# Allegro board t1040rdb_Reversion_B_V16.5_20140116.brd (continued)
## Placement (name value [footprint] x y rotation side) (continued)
C897  0.1uF  [0402]  12.06 59.31 0 top
C898  0.1uF  [0402]  10.03 61.34 270 top
C899  1uF  [0402O]  173.29 62.65 90 bottom
C900  1uF  [0402O]  171.29 68.65 90 bottom
C901  1uF  [0402O]  171.79 61.15 0 bottom
C902  1uF  [0402O]  171.29 62.65 90 bottom
C903  1uF  [0402O]  170.29 64.65 270 bottom
C904  22uF  [0603]  136.27 108.71 0 bottom
C905  22uF  [0603]  136.27 104.52 0 top
C906  22uF  [0603]  136.27 114.81 0 bottom
C907  22uF  [0603]  136.27 104.14 0 bottom
C908  22uF  [0603]  136.27 105.66 0 bottom
C909  22uF  [0603]  136.27 113.28 0 bottom
C910  22uF  [0603]  136.27 109.09 0 top
C911  22uF  [0603]  136.27 107.19 0 bottom
C912  1uF  [0402]  166.02 116.15 270 bottom
C913  1uF  [0402]  166.02 118.25 90 bottom
C914  1uF  [0402]  166.02 111.94 270 bottom
C915  1uF  [0402]  166.02 114.05 270 bottom
C916  0.1uF  [0201]  167.32 110.04 0 bottom
C917  0.1uF  [0201]  168.92 111.64 0 bottom
C918  0.1uF  [0201]  167.32 110.84 180 bottom
C919  0.1uF  [0201]  168.92 110.84 180 bottom
C920  1500pF  [0201]  164.11 110.04 180 bottom
C921  1500pF  [0201]  164.11 110.84 0 bottom
C922  1500pF  [0201]  162.51 110.84 0 bottom
C923  1500pF  [0201]  162.51 112.44 0 bottom
C924  0.33uF  [0603]  197.87 75.31 270 top
C925  22uF  [1206]  194.06 79.76 90 bottom
C926  22uF  [1206]  216.79 136.91 90 bottom
C927  0.47uF  [0603]  218.19 132.46 270 top
C928  1uF  [0603]  196.98 83.44 0 top
C929  1uF  [0603]  217.3 140.59 0 top
C930  22uF  [1206]  196.47 79.76 90 bottom
C931  22uF  [1206]  214.38 136.91 90 bottom
C932  1uF  [0402]  221.49 132.97 90 top
C933  0.1uF  [0402]  187.96 83.57 0 bottom
C934  47uF  [0805]  208.03 132.59 0 bottom
C935  0.1uF  [0402]  203.33 80.9 270 top
C936  47uF  [0805]  208.03 134.75 0 bottom
C937  47uF  [0805]  187.71 81.92 0 bottom
C938  0.01uF  [0402]  201.17 75.82 90 top
C939  47uF  [0805]  187.71 79.76 0 bottom
C940  0.1uF  [0402]  208.28 140.72 0 bottom
C941  0.1uF  [0402]  223.65 138.05 270 top
C942  510pF  [0402]  201.8 80.39 0 top
C943  560pF  [0402]  222.12 137.54 0 top
C944  1uF  [0402]  198.37 81.79 270 bottom
C945  0.01uF  [0402]  199.39 80.77 270 bottom
C946  1uF  [0402]  218.69 138.94 270 bottom
C947  0.1uF  [0402]  219.71 137.92 270 bottom
C948  0.47uF  [0603]  23.24 116.59 90 top
C949  0.47uF  [0603]  23.24 105.79 90 top
C950  1uF  [0603]  25.53 116.46 180 top
C951  1uF  [0603]  24.13 97.66 180 top
C952  22uF  [1206]  27.05 112.14 270 bottom
C953  22uF  [1206]  24.64 112.14 270 bottom
C954  22uF  [1206]  24.64 101.35 270 bottom
C955  22uF  [1206]  27.05 101.35 270 bottom
C956  0.01uF  [0402]  19.94 116.08 270 top
C957  0.01uF  [0402]  19.94 105.28 270 top
C958  47uF  [0805]  33.4 105.66 180 bottom
C959  47uF  [0805]  33.4 112.14 180 bottom
C960  47uF  [0805]  33.4 109.98 180 bottom
C961  0.1uF  [0402]  33.15 108.33 180 bottom
C962  47uF  [0805]  33.4 103.51 180 bottom
C963  0.1uF  [0402]  33.15 97.54 180 bottom
C964  0.1uF  [0402]  17.78 111 90 top
C965  0.1uF  [0402]  17.78 100.2 90 top
C966  560pF  [0402]  19.3 111.51 180 top
C967  620pF  [0402]  19.3 100.71 180 top
C968  1uF  [0402]  22.73 110.11 90 bottom
C969  0.01uF  [0402]  21.72 111.12 90 bottom
C970  1uF  [0402]  22.73 99.31 90 bottom
C971  0.01uF  [0402]  21.72 100.33 90 bottom
C972  1uF  [0603]  60.71 84.84 90 top
C973  1uF  [0603]  62.99 84.71 180 top
C974  1uF  [0603]  24.13 86.87 180 top
C975  22uF  [1206]  62.1 80.39 270 bottom
C976  22uF  [1206]  64.52 80.39 270 bottom
C977  0.01uF  [0402]  57.4 84.33 270 top
C978  1uF  [0603]  23.24 95 90 top
C979  22uF  [1206]  24.64 90.55 270 bottom
C980  22uF  [1206]  27.05 90.55 270 bottom
C981  0.01uF  [0402]  19.94 94.49 270 top
C982  47uF  [0805]  70.87 78.23 180 bottom
C983  47uF  [0805]  70.87 80.39 180 bottom
C984  0.1uF  [0402]  70.61 76.58 180 bottom
C985  47uF  [0805]  33.4 87.12 180 bottom
C986  47uF  [0805]  33.4 95.25 180 bottom
C987  0.1uF  [0402]  32.77 95.38 180 top
C988  0.1uF  [0402]  55.24 79.25 90 top
C989  0.1uF  [0402]  17.78 89.41 90 top
C990  680pF  [0402]  56.77 79.76 180 top
C991  680pF  [0402]  19.3 89.92 180 top
C992  1uF  [0402]  60.2 78.36 90 bottom
C993  0.01uF  [0402]  59.18 79.38 90 bottom
C994  1uF  [0402]  22.73 88.52 90 bottom
C995  0.01uF  [0402]  21.72 89.54 90 bottom
C996  0.01uF  [0402]  201.93 131.19 90 top
C997  0.1uF  [0402]  107.19 78.61 0 top
C998  0.1uF  [0402]  175.89 163.7 90 top
C999  0.1uF  [0402]  184.91 163.19 0 top
C1000  0.1uF  [0603]  107.82 98.81 0 top
C1001  0.1uF  [0603]  107.82 108.97 0 top
C1002  0.1uF  [0402]  21.46 65.02 90 top
C1003  1500pF  [0201]  164.11 116.45 0 bottom
C1004  1500pF  [0201]  170.52 110.84 180 bottom
C1005  1500pF  [0201]  168.92 109.24 180 bottom
C1006  1500pF  [0201]  167.32 109.24 180 bottom
C1007  1500pF  [0201]  164.11 114.85 0 bottom
C1008  1500pF  [0201]  162.51 114.85 0 bottom
C1009  1500pF  [0201]  164.11 115.65 180 bottom
C1010  1500pF  [0201]  162.51 115.65 180 bottom
C1011  0.1uF  [0201]  160.91 117.25 180 bottom
C1012  0.1uF  [0201]  160.91 116.45 180 bottom
C1013  NFM21PC225B0J3  [NFM21]  196.98 125.35 0 top
C1014  NFM21PC225B0J3  [NFM21]  196.98 128.65 180 top
C1015  1uF  [0402]  212.34 125.22 0 top
C1016  1uF  [0402]  211.84 126.75 270 top
C1017  10uF  [0603]  201.68 126.49 90 top
C1018  0.1uF  [0402]  176.91 57.53 90 bottom
C1019  0.1uF  [0402]  176.91 72.26 180 bottom
C1020  0.1uF  [0402]  176.91 64.14 180 bottom
C1021  0.1uF  [0402]  176.91 63.12 180 bottom
C1022  0.1uF  [0402]  155.32 100.33 180 bottom
C1023  0.01uF  [0402]  45.85 132.84 180 top
C1024  0.01uF  [0402]  48.89 132.84 0 top
C1025  0.1uF  [0402]  196.47 62.48 90 bottom
C1026  0.1uF  [0201]  173.72 109.24 0 bottom
C1027  0.1uF  [0201]  170.52 112.44 180 bottom
C1028  0.1uF  [0201]  164.51 108.04 270 bottom
C1029  0.1uF  [0201]  164.11 113.25 180 bottom
C1030  0.1uF  [0201]  164.11 112.44 0 bottom
C1031  0.1uF  [0201]  162.51 111.64 180 bottom
C1032  0.1uF  [0201]  164.11 111.64 180 bottom
C1033  0.1uF  [0201]  164.11 109.24 0 bottom
C1034  0.1uF  [0201]  170.52 109.24 180 bottom
C1035  0.1uF  [0201]  162.51 113.25 180 bottom
C1036  0.1uF  [0201]  170.92 108.04 270 bottom
C1037  0.1uF  [0201]  170.52 111.64 0 bottom
C1038  0.1uF  [0201]  170.52 110.04 0 bottom
C1039  0.1uF  [0201]  168.92 110.04 0 bottom
C1040  10uF  [0603]  235.2 132.21 180 bottom
C1041  0.01uF  [0402]  235.08 133.98 90 bottom
C1044  0.1uF  [0402]  238.76 138.05 180 bottom
C1045  0.1uF  [0402]  235.58 138.94 270 bottom
C1046  0.1uF  [0402]  233.68 137.79 0 bottom
C1047  0.1uF  [0402]  233.93 135.51 0 bottom
C1048  0.1uF  [0402]  238.63 135.51 180 bottom
C1049  10uF  [0603]  233.68 129.92 270 bottom
C1050  0.1uF  [0402]  238.76 137.03 180 bottom
C1051  0.1uF  [0402]  233.3 139.83 90 bottom
C1052  0.1uF  [0402]  237.36 133.98 90 bottom
C1053  1uF  [0603]  215.9 132.59 0 top
C1054  1uF  [0603]  195.58 75.44 0 top
C1055  1uF  [0603]  24.13 108.46 180 top
C1056  1uF  [0603]  25.53 105.66 180 top
C1057  1uF  [0603]  61.59 76.71 180 top
C1058  1uF  [0603]  25.53 94.87 180 top
C1059  0.1uF  [0402]  91.44 129.16 180 bottom
C1060  0.1uF  [0402]  93.47 129.16 0 bottom
C1061  0.1uF  [0402]  91.44 123.32 180 bottom
C1062  0.1uF  [0402]  93.47 123.32 0 bottom
C1063  47uF  [0805]  187.71 77.6 0 bottom
C1064  47uF  [0805]  187.71 75.44 0 bottom
C1066  47uF  [0805]  33.4 93.22 180 bottom
C1067  47uF  [0805]  33.4 91.19 180 bottom
C1068  47uF  [0805]  33.4 89.15 180 bottom
C1069  47uF  [0805]  208.03 136.91 0 bottom
C1070  47uF  [0805]  208.03 139.06 0 bottom
C1071  0.1uF  [0402]  82.42 127.38 0 bottom
C1072  0.1uF  [0402]  80.39 127.38 180 bottom
C1073  0.1uF  [0402]  82.42 133.48 0 bottom
C1074  0.1uF  [0402]  80.39 133.48 180 bottom
C1075  10uF  [1206]  17.15 83.69 90 top
C1076  0.1uF  [0603]  16.76 73.79 270 top
C1077  10uF  [1206]  19.56 83.69 90 top
C1078  0.01uF  [0402]  18.03 73.91 270 top
C1079  0.1uF  [0402]  200.41 126.49 90 top
C1080  220uF  [CAPE_B8]  262.38 161.92 180 top
C1081  0.1uF  [0402]  271.65 153.54 0 bottom
C1082  0.1uF  [0402]  207.14 62.74 180 bottom
C1083  0.1uF  [0402]  214.88 70.1 90 bottom
C1084  0.1uF  [0402]  213.61 69.22 90 bottom
C1085  0.1uF  [0402]  241.43 62.74 180 bottom
C1086  0.1uF  [0402]  248.03 66.68 180 bottom
C1087  0.1uF  [0402]  248.03 67.69 180 bottom
C1088  1uF  [0402O]  167.29 64.65 90 bottom
C1089  1uF  [0402O]  166.29 66.65 90 bottom
C1090  1uF  [0402O]  167.29 66.65 90 bottom
C1091  1uF  [0402O]  165.29 68.65 90 bottom
C1092  1uF  [0402O]  166.29 68.65 90 bottom
C1093  1uF  [0402O]  167.29 68.65 90 bottom
C1094  1uF  [0402O]  170.29 68.65 90 bottom
C1095  47uF  [0805]  33.4 116.46 180 bottom
C1096  47uF  [0805]  33.4 114.3 180 bottom
C1097  47uF  [0805]  33.4 101.35 180 bottom
C1098  47uF  [0805]  33.4 99.19 180 bottom
C1099  47uF  [0805]  70.87 84.71 180 bottom
C1100  47uF  [0805]  70.87 82.55 180 bottom
C1101  0.1uF  [0402O]  65.52 105.93 0 bottom
C1102  0.1uF  [0402O]  64.02 104.42 90 bottom
C1103  0.1uF  [0402O]  65.02 104.42 90 bottom
C1104  0.1uF  [0402O]  71.52 112.93 180 bottom
C1105  0.1uF  [0402O]  71.52 113.93 0 bottom
C1106  22uF  [0603]  136.27 110.62 0 top
C1107  22uF  [0603]  136.27 112.14 0 top
C1108  22uF  [0603]  140.21 104.9 270 bottom
C1109  22uF  [0603]  141.73 104.9 270 bottom
C1110  22uF  [0603]  141.73 109.47 90 bottom
C1111  22uF  [0603]  140.21 109.47 90 bottom
C1112  22uF  [1206]  28.45 94.36 0 bottom
C1113  22uF  [1206]  21.21 94.36 180 bottom
D1  GRN  [LED_0603]  71.63 91.69 90 top
D3  CMHD3595  [SOD123]  58.93 23.62 180 top
D4  CMHD3595  [SOD123]  65.28 27.94 90 top
D5  GRN  [LED_0603]  40.89 84.84 180 top
D6  GRN  [LED_0603]  40.89 82.55 180 top
D22  RB521  [SOD523]  117.86 28.58 180 top
D25  ES1D-13-F  [SMA]  38.1 76.33 90 top
D26  MURS120-13-F  [SMB]  49.15 49.66 180 top
D27  BAW56-7-F  [SOT23]  71.12 50.55 180 bottom
D28  MURS120-13-F  [SMB]  50.29 55.88 90 top
D30  RB521  [SOD523]  77.85 147.07 0 top
D31  RB521  [SOD523]  69.98 151.38 270 top
D33  BAT43WS  [SOD323]  58.17 135.25 270 top
D34  RB521  [SOD523]  58.42 126.75 180 top
D35  RB521  [SOD523]  15.62 62.99 0 top
D36  GRN  [LED_PM_1S]  53.72 1.14 0 top
D37  GRN  [LED_PM_1S]  58.04 1.14 0 top
D38  GRN  [LED_PM_1S]  32.13 1.14 0 top
D39  GRN  [LED_PM_1S]  36.45 1.14 0 top
D40  GRN  [LED_PM_1S]  49.4 1.14 0 top
D41  GRN  [LED_PM_1S]  40.77 1.14 0 top
D42  GRN  [LED_PM_1S]  45.09 1.14 0 top
D43  GRN  [LED_PM_1S]  27.81 1.14 0 top
D44  GRN  [LED_PM_1S]  23.49 1.14 0 top
F1  3A/60V  [PTC_SM013]  96.27 31.5 270 top
F2  3A/60V  [PTC_SM013]  91.82 31.5 270 top
F3  3A/60V  [PTC_SM013]  87.38 31.5 270 top
F4  3A/60V  [PTC_SM013]  82.93 31.5 270 top
F5  3A/60V  [PTC_SM013]  114.05 31.5 270 top
F6  3A/60V  [PTC_SM013]  109.6 31.5 270 top
F7  3A/60V  [PTC_SM013]  105.16 31.5 270 top
F8  3A/60V  [PTC_SM013]  100.71 31.5 270 top
F9  500mA  [1206]  34.67 241.05 0 top
F10  500mA  [1206]  64.26 137.79 0 top
F11  500mA  [1206]  174.37 241.05 0 top
F12  500mA  [1206]  104.52 241.05 0 top
F13  500mA  [1206]  244.22 241.05 0 top
FB6  BLM21PG121SN1  [0805]  66.42 19.56 90 top
FB7  BLM21PG121SN1  [0805]  73.53 19.56 90 bottom
FB8  BLM21PG121SN1  [0805]  64.39 19.56 90 top
FB9  BLM21PG121SN1  [0805]  73.53 19.56 90 top
FB10  BLM18BD601SN1  [0603]  80.14 89.66 90 top
FB11  BLM18PG121SN1  [0603]  161.92 98.3 270 bottom
FB12  BLM18PG121SN1  [0603]  159.64 98.04 0 bottom
FB13  BLM18PG121SN1  [0603]  156.59 98.04 180 bottom
FB18  BLM18BD601SN1  [0603]  122.94 39.5 0 top
FB19  BLM18BD601SN1  [0603]  122.94 36.45 0 top
FB20  BLM18BD601SN1  [0603]  122.94 37.97 0 top
FB21  BLM18BD601SN1  [0603]  122.94 34.92 0 top
FB22  BLM18BD601SN1  [0603]  122.94 30.35 0 top
FB23  BLM18BD601SN1  [0603]  122.94 31.88 0 top
FB24  BLM18BD601SN1  [0603]  122.94 28.83 0 top
FB25  BLM18BD601SN1  [0603]  122.94 33.4 0 top
FB26  BLM18BD601SN1  [0603]  166.24 43.56 0 top
FB29  BLM18BD601SN1  [0603]  135 41.66 270 top
FB32  BLM18BD601SN1  [0603]  184.91 54.36 270 top
FB35  BLM18PG121SN1  [0603]  218.44 73.66 270 bottom
FB36  BLM18PG121SN1  [0603]  203.2 64.52 180 bottom
FB37  BLM18PG121SN1  [0603]  252.73 73.66 270 bottom
FB38  BLM18PG121SN1  [0603]  237.49 64.52 180 bottom
FB39  BLM18BD601SN1  [0603]  260.99 62.74 270 top
FB40  BLM18PG121SN1  [0603]  175.64 57.15 90 bottom
FB41  BLM18PG121SN1  [0603]  177.29 70.99 180 bottom
FB42  BLM18PG121SN1  [0603]  177.29 65.41 180 bottom
FB43  BLM18PG121SN1  [0603]  177.29 61.85 180 bottom
FB44  BLM21PG121SN1  [0805]  178.31 48.51 270 bottom
FB45  BLM21PG121SN1  [0805]  176.28 48.51 270 bottom
FB46  BLM21PG121SN1  [0805]  59.82 45.59 0 top
FB47  BLM18BD601SN1  [0603]  47.88 112.65 0 top
FB48  BLM18BD601SN1  [0603]  80.14 98.17 90 top
FB50  BLM18BD601SN1  [0603]  80.14 106.55 90 top
FB52  BLM18BD601SN1  [0603]  153.16 71.76 0 top
FB53  BLM18BD601SN1  [0603]  234.82 77.98 180 top
FB54  BLM18PG221SN1  [0603]  232.16 134.62 270 bottom
FB55  BLM18PG221SN1  [0603]  232.16 131.57 270 bottom
J1  DDR3_DIMM  [CON_DDR3_DIMM]  153.42 158.5 0 top
J2  SD_CARD_SKT  [CON_SD]  39.02 4.02 180 bottom
J3  HTST-108-01-L-DV  [HDR_P254_HTST_2X8]  11.18 138.18 180 top
J9  JMP2  [JMP_P254_T_1X2]  57.53 148.34 270 top
J10  JMP2  [JMP_P254_T_1X2]  57.53 145.16 270 top
J11  JMP2  [JMP_P254_T_1X2]  57.53 151.51 270 top
J13  RJ45_2X1  [CON_RJ45_2X1]  141.02 -1.48 0 top
J14  RJ45_LED_2X1  [CON_RJ45_2X1_LED]  159.52 -1.48 0 top
J15  RJ45_LED_8  [CON_RJ45_2X4_LED]  237.02 -1.48 0 top
J16  SFP+_CONN  [CON_SFP]  177.52 4.02 0 top
J17  SFP_CAGE  [CON_SFP_CAGE]  177.52 4.02 0 top
J18  PCIE_X4  [CON_PEX4]  272.8 93.73 90 top
J19  MINIPCIE_CONN  [CON_MINIPCIE]  183.9 201.68 90 top
J20  MINIPCIE_CONN  [CON_MINIPCIE]  84.84 201.68 270 top
J21  SATA_CONN  [CON_SATA]  255.02 110.24 90 top
J22  RJ11_6P_2  [CON_RJ11_6P_2X1]  86.52 -0.98 0 top
J23  RJ11_6P_2  [CON_RJ11_6P_2X1]  101.52 -0.98 0 top
J24  RJ11_4P  [CON_RJ11_4P_1X1]  115.52 -0.98 0 top
J25  TQ2-3V  [RELAY_TQ2]  115.52 19.52 180 top
J26  HDR_2X5  [HDR_P254_M_T_2X5]  16.89 124.21 270 top
J27  JMP2  [JMP_P254_T_1X2]  82.68 80.9 180 top
J28  HDR_1X3  [HDR_P254_M_T_1X3]  74.68 88.9 180 top
J30  BAT_SOCKET  [CON_BAT_WBA3B2]  91.19 150.24 180 top
J31  JMP2  [JMP_P254_T_1X2]  77.72 149.61 180 top
J32  JMP3  [HDR_P254_M_T_1X3]  67.44 151.51 270 top
J33  CON_3PIN  [CON_WAFER_P254_S_1X3]  35.94 245.49 180 top
J34  CON_3PIN  [CON_WAFER_P254_S_1X3]  66.55 132.33 90 top
J35  JMP2  [JMP_P254_T_1X2]  66.55 126.37 270 top
J37  ATX_PWR_CONN_20PIN  [CON_ATX_20PIN]  10.54 94.36 270 top
J39  JMP2  [JMP_P254_T_1X2]  222.5 141.73 90 top
J41  USB_A_2  [CON_USB_A_2]  69.02 -0.98 0 top
J42  RJ45_LED  [CON_RJ45_UP_1X1_LED]  195.52 -1.48 0 top
J43  CONN_2X20  [CON_MEC6_120]  272.8 152.06 0 top
J44  CON_3PIN  [CON_WAFER_P254_S_1X3]  175.64 245.49 180 top
J45  CON_3PIN  [CON_WAFER_P254_S_1X3]  105.79 245.49 180 top
J46  CON_3PIN  [CON_WAFER_P254_S_1X3]  245.49 245.49 180 top
L1  90ohm  [IND_CM_2012]  73.79 28.83 270 bottom
L2  90ohm  [IND_CM_2012]  76.33 28.83 270 bottom
L3  2.2uH  [IND_SWPA2520]  152.91 46.1 180 top
L4  2.2uH  [IND_SWPA2520]  130.68 46.74 180 top
L5  4.7uH  [IND_SWPA2520]  184.02 57.66 180 top
L6  220uH  [IND_SWRB07]  32.77 68.33 90 top
L7  100uH  [IND_SWRB07]  41.66 68.33 90 top
L8  215nH  [IND_FP1007]  117.48 94.23 0 top
L9  215nH  [IND_FP1007]  117.48 104.39 0 top
L16  22uH  [IND_45X40]  59.69 130.43 90 top
L17  2.2uH  [IND_IHLP_2525]  189.61 79.76 180 top
L18  2.2uH  [IND_IHLP_2525]  209.93 136.91 180 top
L19  3.3uH  [IND_IHLP_2525]  31.5 112.14 0 top
L20  3.3uH  [IND_IHLP_2525]  31.5 101.35 0 top
L21  4.7uH  [IND_IHLP_2525]  68.96 80.39 0 top
L22  2.2uH  [IND_IHLP_2525]  31.5 90.55 0 top
L23  1uH  [IND_IHLP_2525]  24.89 81.79 180 top
M2  HEATSINK_FAN  [HS_T1040]  166.12 114.05 0 top
M3  MH  [MH_580S340P]  261 189.58 180 top
M4  MH  [MH_580S340P]  237.18 189.58 0 top
M5  MH  [MH_580S340P]  261 213.78 180 top
M6  MH  [MH_580S340P]  237.18 213.78 0 top
M7  MH  [MH_580S340P]  207.8 189.58 180 top
M8  MH  [MH_580S340P]  231.95 189.58 180 top
M9  MH  [MH_580S340P]  231.95 213.78 180 top
M10  MH  [MH_580S340P]  207.8 213.78 180 top
M11  MH  [MH_580S340P]  31.56 189.58 0 top
M12  MH  [MH_580S340P]  31.56 213.78 0 top
M13  MH  [MH_580S340P]  7.74 189.58 0 top
M14  MH  [MH_580S340P]  7.74 213.78 0 top
M15  MH  [MH_580S340P]  36.79 189.58 0 top
M16  MH  [MH_580S340P]  36.79 213.78 0 top
M17  MH  [MH_580S340P]  60.94 189.58 0 top
M18  MH  [MH_580S340P]  60.94 213.78 0 top
NOREF  val  [unnamed]  166.12 114.05 270 top
NOREF#2  -  [#2]  -252.98 -202.18 0 top
Q1  IRLML6346  [SOT23]  169.29 89.54 90 bottom
Q2  IRLML6346  [SOT23]  165.23 89.54 270 bottom
Q3  IRLML6346  [SOT23]  62.36 35.94 90 top
Q4  IRLML6346  [SOT23]  57.66 35.94 90 top
Q5  MMBT2907A  [SOT23]  71.25 64.39 270 bottom
Q6  IRLZ24NSPBF  [TO263]  64.52 67.69 90 top
Q7  FDV301N  [SOT23]  74.55 67.69 270 bottom
Q8  IRFH6200  [SO_8_FL]  129.03 112.78 270 bottom
Q9  IRFH6200  [SO_8_FL]  129.03 106.43 270 bottom
Q11  IRFHM4226  [U8_FL]  37.97 99.82 90 top
Q12  IRF9321  [SO_8]  24.51 75.31 0 top
Q13  IRLML6346  [SOT23]  129.03 112.4 270 top
Q15  IRLML6346  [SOT23]  38.35 104.01 180 top
Q16  IRLML6346  [SOT23]  19.05 70.87 0 top
Q17  IRFHM4226  [U8_FL]  75.44 78.87 90 top
Q18  IRFH6200  [SO_8_FL]  39.24 89.15 90 top
Q20  IRLML6346  [SOT23]  75.82 83.06 180 top
Q21  IRLML6346  [SOT23]  38.23 94.36 180 top
Q23  IRFHM4226  [U8_FL]  44.07 128.91 90 top
Q24  IRFHM4226  [U8_FL]  49.02 128.91 270 top
Q25  IRLML6346  [SOT23]  46.23 119.25 0 top
Q26  IRLML6346  [SOT23]  49.91 119.25 0 top
Q27  IRLML6346  [SOT23]  54.86 125.6 0 top
Q28  IRLML6346  [SOT23]  54.86 129.67 0 top
Q29  IRLML2502  [SOT23]  54.86 133.73 0 top
Q30  MMBT4401  [SOT23]  9.53 67.82 0 top
Q31  IRFHM4226  [U8_FL]  203.45 135.38 270 top
Q32  IRLML6346  [SOT23]  204.34 131.06 0 top
Q33  IRLML2030  [SOT23]  44.07 143.64 90 top
Q34  IRLML2030  [SOT23]  48.13 143.64 90 top
Q35  IRLML6346  [SOT23]  42.93 135.64 0 top
Q36  IRLML6346  [SOT23]  47.88 136.4 0 top
Q37  IRLML6346  [SOT23]  152.91 132.21 90 bottom
Q38  IRLML6346  [SOT23]  152.91 128.52 90 bottom
Q39  IRLML6346  [SOT23]  168.53 88.77 90 top
Q40  IRLML6346  [SOT23]  168.53 84.84 180 top
Q41  IRLML6346  [SOT23]  273.56 135.89 270 top
Q42  IRFHM4226  [U8_FL]  44.07 124.59 270 top
Q43  IRFHM4226  [U8_FL]  50.67 124.59 90 top
Q44  IRLML2030  [SOT23]  41.53 139.7 0 top
Q45  IRLML2030  [SOT23]  45.21 139.7 0 top
R1  162  [0402]  169.42 125.6 180 bottom
R2  1K  [0402]  152.53 163.19 180 top
R3  162  [0402]  166.5 124.84 135 bottom
R4  10K  [0402]  161.8 163.19 0 top
R5  4.7K  [0402]  150.24 112.9 270 bottom
R6  4.7K  [0402]  73.32 113.73 90 bottom
R7  4.7K  [0402]  71.82 115.23 0 bottom
R9  4.7K  [0402]  59.01 115.83 90 bottom
R10  4.7K  [0402]  60.01 115.83 90 bottom
R11  4.7K  [0402]  61.01 115.83 90 bottom
R12  10  [0402]  153.42 115.57 180 bottom
R13  4.7K  [0402]  113.41 125.35 0 bottom
R14  33  [0402]  123.06 120.9 180 bottom
R15  33  [0402]  123.06 121.92 180 bottom
R16  33  [0402]  123.06 122.94 180 bottom
R17  4.7K  [0402]  72.77 142.75 270 bottom
R18  33  [0402]  121.03 123.57 180 bottom
R19  4.7K  [0402]  74.04 142.75 270 bottom
R20  33  [0402]  123.06 124.21 180 bottom
R21  4.7K  [0402]  75.31 142.75 270 bottom
R22  33  [0402]  121.03 124.84 180 bottom
R23  4.7K  [0402]  76.58 142.75 270 bottom
R24  33  [0402]  123.06 125.48 180 bottom
R25  4.7K  [0402]  77.85 142.75 270 bottom
R26  33  [0402]  121.03 126.11 180 bottom
R27  4.7K  [0402]  79.12 142.75 270 bottom
R28  33  [0402]  123.06 126.75 180 bottom
R29  4.7K  [0402]  80.39 142.75 270 bottom
R30  33  [0402]  123.06 127.76 180 bottom
R31  4.7K  [0402]  81.66 142.75 270 bottom
R32  33  [0402]  123.06 128.78 180 bottom
R33  4.7K  [0402]  85.47 142.75 270 bottom
R34  4.7K  [0402]  86.74 142.75 270 bottom
R35  4.7K  [0402]  88.01 142.75 270 bottom
R36  4.7K  [0402]  89.28 142.75 270 bottom
R37  4.7K  [0402]  90.55 142.75 270 bottom
R38  4.7K  [0402]  93.09 142.75 270 bottom
R39  4.7K  [0402]  91.82 142.75 270 bottom
R40  4.7K  [0402]  94.36 142.75 270 bottom
R41  4.7K  [0402]  118.75 129.41 180 bottom
R42  4.7K  [0402]  104.27 124.21 0 bottom
R43  4.7K  [0402]  102.11 134.49 90 bottom
R44  4.7K  [0402]  118.75 130.43 180 bottom
R45  4.7K  [0402]  97.03 126.11 0 bottom
R46  4.7K  [0402]  97.54 127.64 270 bottom
R47  4.7K  [0402]  118.75 128.4 180 bottom
R48  1K  [0402]  97.03 125.09 0 bottom
R49  0  [0402]  89.41 127.13 0 bottom
R50  0  [0402]  89.41 128.14 0 bottom
R51  0  [0402]  77.72 126.11 180 bottom
R52  0  [0402]  78.36 133.48 0 bottom
R54  4.7K  [0402]  254.63 131.95 90 top
R55  4.7K  [0402]  270.51 138.05 270 top
R56  4.7K  [0402]  255.14 133.73 180 top
R57  4.7K  [0402]  269.62 133.6 90 top
R58  33  [0402]  255.65 131.95 90 top
R59  10  [0402]  161.54 93.73 270 top
R60  10K  [0402]  155.45 94.74 90 bottom
R61  0  [0402]  163.19 102.36 270 bottom
R62  10K  [0402]  154.43 94.74 90 bottom
R63  10K  [0402]  160.53 94.74 90 bottom
R64  10K  [0402]  159.51 94.74 90 bottom
R65  10K  [0402]  153.42 94.74 90 bottom
R66  10K  [0402]  157.48 94.74 90 bottom
R67  10K  [0402]  158.5 94.74 90 bottom
R68  10K  [0402]  156.46 94.74 90 bottom
R69  4.7K  [0402]  71.02 108.63 0 bottom
R70  4.7K  [0402]  71.02 109.63 0 bottom
R71  4.7K  [0402]  153.29 106.43 180 bottom
R72  4.7K  [0402]  70.32 102.42 180 bottom
R73  4.7K  [0402]  153.29 103.38 180 bottom
R74  4.7K  [0402]  153.29 104.39 180 bottom
R75  4.7K  [0402]  172.08 98.3 90 bottom
R76  4.7K  [0402]  174.12 98.3 90 bottom
R77  4.7K  [0402]  172.08 101.6 270 bottom
R78  4.7K  [0402]  173.1 98.3 90 bottom
R79  4.7K  [0402]  162.31 91.95 270 bottom
R80  4.7K  [0402]  169.04 101.09 270 bottom
R81  4.7K  [0402]  74.04 105.16 0 bottom
R82  4.7K  [0402]  153.42 116.59 180 bottom
R83  1K  [0402]  73.52 111.13 90 bottom
R84  1K  [0402]  153.29 105.41 180 bottom
R85  4.7K  [0402]  70.32 103.42 180 bottom
R86  4.7K  [0402]  170.05 98.3 90 bottom
R87  4.7K  [0402]  169.04 98.3 90 bottom
R88  4.7K  [0402]  165.35 93.73 0 bottom
R89  4.7K  [0402]  169.42 92.46 90 bottom
R90  4.7K  [0402]  241.68 148.72 0 top
R91  4.7K  [0402]  241.68 149.86 0 top
R92  4.7K  [0402]  168.02 98.3 90 bottom
R93  4.7K  [0402]  170.05 101.09 270 bottom
R94  4.7K  [0402]  72.02 111.63 180 bottom
R95  4.7K  [0402]  171.07 101.09 270 bottom
R96  4.7K  [0402]  72.02 110.63 180 bottom
R97  4.7K  [0402]  171.07 98.3 90 bottom
R98  4.7K  [0402]  70.32 104.42 0 bottom
R99  4.7K  [0402]  257.56 154.94 270 top
R100  10  [0402]  166.12 105.54 90 bottom
R101  4.7K  [0402]  77.22 98.68 0 top
R102  4.7K  [0402]  68.96 137.41 0 top
R103  510  [0402]  71.63 94.36 270 top
R104  698  [0402]  153.42 118.62 0 bottom
R105  698  [0402]  153.42 117.6 0 bottom
R106  10K  [0402]  136.4 128.02 0 bottom
R107  10K  [0402]  20.07 153.42 180 top
R108  10  [0402]  20.07 141.99 0 top
R109  10K  [0402]  20.07 139.45 0 top
R110  10K  [0402]  20.07 150.88 180 top
R111  10K  [0402]  20.07 140.72 180 top
R112  10K  [0402]  20.07 143.26 180 top
R113  10K  [0402]  20.07 145.8 180 top
R114  10K  [0402]  20.07 148.34 180 top
R115  10  [0402]  175.13 101.6 90 bottom
R116  10  [0402]  176.15 101.6 90 bottom
R117  10  [0402]  179.32 106.3 0 bottom
R118  10  [0402]  181.36 106.81 0 bottom
R119  10  [0402]  174.12 101.6 90 bottom
R120  10  [0402]  181.36 105.79 0 bottom
R121  10  [0402]  173.1 101.6 90 bottom
R122  10  [0402]  179.32 105.28 0 bottom
R123  4.7K  [0402]  178.56 103.51 0 bottom
R124  4.7K  [0402]  179.32 108.97 180 bottom
R125  10  [0402]  179.2 101.98 90 bottom
R126  10  [0402]  181.36 108.97 0 bottom
R127  10  [0402]  177.67 101.35 0 bottom
R128  10  [0402]  181.36 107.82 0 bottom
R129  10  [0402]  181.36 104.78 180 bottom
R130  10  [0402]  164.21 102.36 270 bottom
R131  1.5K  [0402]  146.43 56.01 90 top
R132  4.7K  [0402]  146.43 58.8 90 top
R133  510  [0402O]  164.79 65.15 180 bottom
R134  270  [0402O]  164.79 64.15 180 bottom
R135  4.7K  [0402]  187.32 106.43 180 bottom
R136  4.7K  [0402]  187.32 105.41 180 bottom
R137  4.7K  [0402]  187.32 104.39 180 bottom
R138  1K  [0402]  150.5 60.71 0 top
R139  200  [0402]  172.52 111.24 270 bottom
R140  698  [0402]  171.33 119.75 180 bottom
R141  4.7K  [0402]  204.85 84.33 0 top
R142  4.7K  [0402]  232.66 94.36 90 bottom
R143  4.7K  [0402]  232.66 103.25 90 bottom
R155  10K  [0402]  57.02 38.35 0 top
R156  10K  [0402]  61.72 38.48 0 top
R157  0  [0402]  61.72 33.53 0 top
R158  10K  [0402]  60.2 34.04 90 top
R159  10K  [0402]  64.01 33.53 0 top
R160  0  [0402]  58.67 33.53 0 top
R161  1K  [0402]  57.15 33.02 270 top
R162  1K  [0402]  64.52 31.88 270 top
R163  51.1K  [0402]  57.15 26.03 90 top
R164  51.1K  [0402]  66.93 28.19 270 top
R165  18.2K  [0402]  56.13 26.03 270 top
R166  18.2K  [0402]  67.44 29.84 180 top
R167  0  [0402]  74.3 28.83 270 bottom
R168  0  [0402]  73.28 28.83 270 bottom
R169  0  [0402]  76.84 28.83 270 bottom
R170  0  [0402]  75.82 28.83 270 bottom
R171  10K  [0402]  155.32 101.35 0 bottom
R172  49.9  [0402]  155.32 99.31 0 bottom
R173  49.9  [0402]  154.3 102.36 0 bottom
R174  1K  [0402]  80.39 87.12 270 top
R175  33  [0402]  89.79 89.54 0 top
R176  1K  [0402]  89.79 88.52 0 top
R177  330  [0402]  60.45 147.45 180 top
R178  330  [0402]  60.45 146.05 180 top
R179  330  [0402]  59.94 151.13 90 top
R180  0  [0805]  58.8 121.16 0 top
R182  0  [0805]  58.8 119.13 0 top
R183  0  [0805]  54.1 137.41 0 top
R184  0  [0805]  54.1 139.45 0 top
R185  4.7K  [0402]  59.71 98.42 180 bottom
R186  510  [0402]  44.07 84.84 180 top
R187  510  [0402]  44.07 82.55 180 top
R188  5.1  [0402]  153.16 109.35 0 bottom
R189  0.33  [0402]  190.88 124.08 0 bottom
R190  0  [0402]  190.88 125.09 0 bottom
R191  5.1  [0402]  153.16 111.89 0 bottom
R192  0.33  [0402]  190.88 127.89 0 bottom
R193  0  [0402]  190.88 128.91 0 bottom
R194  5.1  [0402]  151.76 105.92 90 bottom
R195  5.1  [0402]  149.35 118.11 90 bottom
R196  100  [0402]  132.59 67.31 270 top
R197  100  [0402]  132.59 65.28 270 top
R198  100  [0402]  137.92 61.09 270 top
R199  100  [0402]  138.94 61.09 270 top
R200  100  [0402]  125.48 67.18 270 top
R201  100  [0402]  125.48 65.15 270 top
R202  100  [0402]  130.81 61.09 270 top
R203  100  [0402]  131.83 61.09 270 top
R204  4.7K  [0402]  58.67 125.48 180 top
R205  100  [0402]  150.37 121.03 180 bottom
R206  100  [0402]  150.37 120.02 180 bottom
R207  75  [0603]  155.7 29.84 180 bottom
R208  75  [0603]  158.75 29.84 180 bottom
R209  33  [0402]  164.08 46.48 180 top
R210  75  [0603]  161.8 29.84 180 bottom
R211  33  [0402]  166.12 50.55 180 top
R212  75  [0603]  164.85 29.84 180 bottom
R213  33  [0402]  164.08 47.5 180 top
R214  33  [0402]  164.08 48.51 180 top
R215  33  [0402]  164.08 49.53 180 top
R216  33  [0402]  164.08 45.47 180 top
R217  33  [0402]  151.38 48.01 180 top
R218  510  [0402]  154.69 56.13 0 top
R219  510  [0402]  152.65 56.13 180 top
R220  100  [0402]  160.02 56.13 270 top
R221  0  [0402]  166.12 51.56 0 top
R222  0  [0402]  156.72 55.63 90 top
R224  15  [0402]  153.42 46.61 180 bottom
R227  2.49K  [0402]  152.91 52.58 270 top
R228  4.7K  [0402]  166.12 46.48 0 top
R229  4.7K  [0402]  166.12 47.5 0 top
R230  4.7K  [0402]  166.12 48.51 0 top
R231  4.7K  [0402]  166.12 49.53 0 top
R232  4.7K  [0402]  166.12 45.47 0 top
R233  4.7K  [0402]  154.69 55.12 0 top
R234  4.7K  [0402]  152.65 55.12 180 top
R235  4.7K  [0402]  157.73 55.63 90 top
R236  75  [0603]  139.83 29.84 180 bottom
R237  75  [0603]  142.88 29.84 180 bottom
R238  33  [0402]  143.89 51.18 180 top
R239  33  [0402]  141.86 47.12 180 top
R240  75  [0603]  145.92 29.84 180 bottom
R241  75  [0603]  148.97 29.84 180 bottom
R242  33  [0402]  141.86 48.13 180 top
R243  33  [0402]  141.86 49.15 180 top
R244  33  [0402]  141.86 50.16 180 top
R245  33  [0402]  141.86 46.1 180 top
R246  33  [0402]  129.16 48.64 180 top
R247  510  [0402]  132.46 56.77 0 top
R248  510  [0402]  130.43 56.77 180 top
R249  100  [0402]  137.79 56.77 270 top
R250  0  [0402]  142.37 53.21 90 top
R251  0  [0402]  134.49 56.26 90 top
R252  4.7K  [0402]  136.78 56.77 90 top
R253  15  [0402]  131.19 47.24 180 bottom
R256  2.49K  [0402]  130.68 53.21 270 top
R257  4.7K  [0402]  143.89 47.12 0 top
R258  4.7K  [0402]  143.89 48.13 0 top
R259  4.7K  [0402]  143.89 49.15 0 top
R260  4.7K  [0402]  143.89 50.16 0 top
R261  4.7K  [0402]  143.89 46.1 0 top
R262  4.7K  [0402]  132.46 55.75 0 top
R263  4.7K  [0402]  130.43 55.75 180 top
R264  4.7K  [0402]  135.51 56.26 90 top
R265  75  [0603]  190.37 19.3 180 bottom
R266  75  [0603]  193.42 19.3 180 bottom
R267  75  [0603]  196.47 19.3 180 bottom
R268  4.7K  [0402]  198.25 66.17 90 top
R269  4.7K  [0402]  198.25 68.2 90 top
R270  4.7K  [0402]  199.26 68.2 90 top
R271  75  [0603]  199.52 19.3 180 bottom
R272  4.7K  [0402]  194.94 72.39 270 top
R273  4.7K  [0402]  195.96 72.39 270 top
R274  510  [0402]  183.39 69.98 90 top
R275  510  [0402]  181.36 70.36 180 top
R276  4.7K  [0402]  181.36 68.2 180 top
R277  4.7K  [0402]  181.36 69.34 0 top
R278  4.7K  [0402]  183.9 68.2 180 top
R279  4.7K  [0402]  184.4 69.98 270 top
R280  100  [0402]  192.28 72.39 270 top
R281  0  [0402]  183.9 67.18 180 top
R282  4.7K  [0402]  193.29 72.39 90 top
R284  15  [0402]  184.28 59.56 180 top
R285  2.49K  [0402]  183.9 65.91 180 top
R286  12.1K  [0402]  198.25 62.86 270 top
R291  0  [0402]  220.85 70.48 90 top
R292  100  [0402]  221.36 67.95 180 top
R293  4.7K  [0402]  203.58 65.02 180 top
R294  4.7K  [0402]  203.58 66.04 180 top
R295  4.7K  [0402]  203.58 64.01 180 top
R296  4.7K  [0402]  222.88 68.45 270 top
R297  4.7K  [0402]  217.42 68.2 180 bottom
R302  1K  [0402]  221.36 68.96 180 top
R303  2K  [0402]  212.47 56.26 90 top
R312  0  [0402]  255.14 70.48 90 top
R313  100  [0402]  255.65 67.95 180 top
R314  4.7K  [0402]  237.87 65.02 180 top
R315  4.7K  [0402]  237.87 66.04 180 top
R316  4.7K  [0402]  237.87 64.01 180 top
R317  4.7K  [0402]  257.18 68.45 270 top
R320  4.7K  [0402]  251.71 68.2 180 bottom
R323  1K  [0402]  255.65 68.96 180 top
R324  2K  [0402]  246.76 56.26 90 top
R331  75  [0603]  249.05 29.34 180 bottom
R332  75  [0603]  214.76 29.34 180 bottom
R333  75  [0603]  246 29.34 180 bottom
R334  75  [0603]  211.71 29.34 180 bottom
R335  75  [0603]  242.95 29.34 180 bottom
R336  75  [0603]  208.66 29.34 180 bottom
R337  75  [0603]  239.9 29.34 180 bottom
R338  75  [0603]  205.61 29.34 180 bottom
R339  510  [0402]  255.65 62.74 0 top
R340  510  [0402]  221.36 62.74 0 top
R341  510  [0402]  255.65 63.75 0 top
R342  510  [0402]  221.36 63.75 0 top
R343  75  [0603]  240.79 43.43 270 bottom
R344  75  [0603]  206.5 43.43 270 bottom
R345  75  [0603]  237.87 43.43 270 bottom
R346  75  [0603]  203.45 43.43 270 bottom
R347  75  [0603]  234.82 43.43 270 bottom
R348  75  [0603]  200.53 43.43 270 bottom
R349  75  [0603]  231.9 43.43 270 bottom
R350  75  [0603]  197.48 43.43 270 bottom
R351  510  [0402]  250.95 65.02 0 bottom
R352  510  [0402]  216.66 65.02 0 bottom
R353  510  [0402]  255.65 61.72 0 top
R354  510  [0402]  221.36 61.72 0 top
R355  75  [0603]  266.19 29.34 180 bottom
R356  75  [0603]  231.9 29.34 180 bottom
R357  75  [0603]  263.14 29.34 180 bottom
R358  75  [0603]  228.85 29.34 180 bottom
R359  75  [0603]  260.1 29.34 180 bottom
R360  75  [0603]  225.81 29.34 180 bottom
R361  75  [0603]  257.05 29.34 180 bottom
R362  75  [0603]  222.76 29.34 180 bottom
R363  510  [0402]  255.65 66.8 0 top
R364  510  [0402]  221.36 66.8 0 top
R365  510  [0402]  252.35 66.04 0 bottom
R366  510  [0402]  218.06 66.04 0 bottom
R367  75  [0603]  258.06 43.43 270 bottom
R368  75  [0603]  223.65 43.43 270 bottom
R369  75  [0603]  255.02 43.43 270 bottom
R370  75  [0603]  220.73 43.43 270 bottom
R371  75  [0603]  251.97 43.43 270 bottom
R372  75  [0603]  217.68 43.43 270 bottom
R373  75  [0603]  249.05 43.43 270 bottom
R374  75  [0603]  214.76 43.43 270 bottom
R375  510  [0402]  221.36 64.77 0 top
R376  510  [0402]  221.36 65.79 0 top
R377  510  [0402]  255.65 64.77 0 top
R378  510  [0402]  255.65 65.79 0 top
R379  4.7K  [0402O]  165.29 66.65 90 bottom
R380  4.7K  [0402O]  164.29 66.65 90 bottom
R381  4.7K  [0402O]  164.79 63.15 180 bottom
R382  4.7K  [0402]  159.89 65.79 270 bottom
R383  4.7K  [0402O]  166.29 64.65 270 bottom
R384  4.7K  [0402O]  168.79 69.15 0 bottom
R385  4.7K  [0402]  160.91 65.79 270 bottom
R386  100  [0402]  178.44 67.82 270 top
R387  4.7K  [0402O]  173.29 66.65 270 bottom
R388  4.7K  [0402]  178.44 69.85 270 top
R389  4.7K  [0402O]  168.29 61.65 270 bottom
R390  4.7K  [0402]  180.09 38.61 90 bottom
R391  4.7K  [0402]  176.02 38.61 90 bottom
R392  4.7K  [0402]  177.04 38.61 90 bottom
R393  4.7K  [0402]  178.05 38.61 90 bottom
R394  510  [0402]  54.48 10.03 0 top
R395  510  [0402]  58.42 10.03 0 top
R396  4.7K  [0402]  175.01 38.61 90 bottom
R397  4.7K  [0402]  173.99 38.61 90 bottom
R398  4.7K  [0402]  255.52 154.94 90 top
R399  4.7K  [0402]  177.42 211.58 270 top
R400  4.7K  [0402]  267.21 93.6 180 top
R401  4.7K  [0402]  267.21 85.85 180 top
R402  4.7K  [0402]  267.21 86.87 180 top
R403  4.7K  [0402]  267.21 87.88 180 top
R404  4.7K  [0402]  256.54 154.94 90 top
R405  4.7K  [0402]  267.21 114.17 180 top
R406  4.7K  [0402]  256.16 144.4 270 top
R407  4.7K  [0402]  255.14 144.4 270 top
R408  4.7K  [0402]  267.21 94.62 180 top
R409  4.7K  [0402]  253.87 154.43 180 top
R410  4.7K  [0402]  253.87 155.45 180 top
R411  4.7K  [0402]  91.31 191.77 90 top
R412  200K  [1206]  95.76 30.86 270 bottom
R413  200K  [1206]  91.31 30.86 270 bottom
R414  3.01K  [0805]  93.34 49.91 270 bottom
R416  3.01K  [0805]  95.5 49.91 270 bottom
R417  51  [0402]  109.86 67.18 270 bottom
R418  51  [0402]  112.9 67.18 270 bottom
R419  33  [0402]  105.28 67.69 180 bottom
R420  4.7K  [0402]  82.55 66.55 180 top
R421  51  [0402]  110.87 67.18 270 bottom
R422  33  [0402]  111.89 67.18 270 bottom
R423  51  [0402]  106.81 67.18 270 bottom
R425  51  [0402]  107.82 67.18 270 bottom
R426  100  [0402]  108.84 67.18 270 bottom
R428  4.7K  [0402]  90.42 67.06 270 top
R429  3.01K  [0805]  77.98 49.91 270 bottom
R430  402K  [0805]  77.09 62.48 270 bottom
R431  3.01K  [0805]  80.14 49.91 270 bottom
R433  402K  [0805]  79.12 62.48 270 bottom
R434  200K  [1206]  86.87 30.86 270 bottom
R435  200K  [1206]  82.42 30.86 270 bottom
R436  47.5K  [0402]  96.27 54.99 90 top
R437  47.5K  [0402]  77.22 54.99 270 top
R438  75K  [0402]  96.77 60.58 180 top
R439  510  [0402]  32.89 10.03 0 top
R440  510  [0402]  37.21 10.03 0 top
R441  200K  [1206]  113.54 30.86 270 bottom
R442  4.7K  [0402]  104.39 67.18 270 top
R444  3.01K  [0805]  118.36 49.91 270 bottom
R445  51  [0402]  109.98 67.18 270 top
R446  51  [0402]  113.03 67.18 270 top
R447  51  [0402]  111 67.18 270 top
R448  33  [0402]  112.01 67.18 270 top
R449  33  [0402]  105.66 67.18 270 top
R450  51  [0402]  107.7 67.18 270 top
R451  200K  [1206]  109.09 30.86 270 bottom
R452  3.01K  [0805]  116.2 49.91 270 bottom
R453  51  [0402]  106.68 67.18 270 top
R455  100  [0402]  108.71 67.18 270 top
R459  3.01K  [0805]  100.84 49.91 270 bottom
R460  402K  [0805]  101.98 62.48 270 bottom
R461  3.01K  [0805]  103 49.91 270 bottom
R463  402K  [0805]  99.95 62.48 270 bottom
R464  200K  [1206]  104.65 30.86 270 bottom
R465  200K  [1206]  100.2 30.86 270 bottom
R466  47.5K  [0402]  119.13 54.99 90 top
R467  47.5K  [0402]  100.08 54.99 270 top
R468  10  [0402]  117.98 29.84 180 top
R469  75K  [0402]  119.63 60.58 180 top
R470  510  [0402]  49.15 10.03 0 top
R471  510  [0402]  41.53 10.03 0 top
R472  510  [0402]  45.85 10.03 0 top
R473  402K  [0402]  96.39 64.77 0 top
R474  402K  [0805]  96.39 68.07 90 top
R475  402K  [0805]  98.43 68.07 90 top
R476  402K  [0805]  120.14 66.04 90 top
R477  402K  [0805]  118.11 66.04 90 top
R478  402K  [0805]  77.72 66.04 90 top
R479  402K  [0805]  100.58 66.04 90 top
R480  200K  [0805]  30.73 74.68 270 top
R481  200K  [0805]  32.77 74.68 270 top
R482  1.8K  [0805]  64.14 50.55 270 bottom
R483  1.8K  [0805]  66.17 50.55 270 bottom
R484  1.8K  [0805]  68.2 50.55 270 bottom
R485  1.8K  [0402]  73.79 64.01 270 bottom
R486  10  [0402]  71.37 66.8 180 bottom
R487  13K  [0402]  71.37 67.82 180 bottom
R488  1K  [0402]  93.34 67.82 0 top
R489  0  [0402]  79.63 66.04 180 bottom
R490  10  [0402]  77.6 67.06 180 bottom
R491  0.02  [1206]  68.83 68.71 90 bottom
R493  13K  [0402]  79.12 67.56 270 bottom
R494  1K  [0402]  48.89 110.87 270 top
R495  33  [0402]  52.7 113.79 0 top
R496  4.7K  [0402]  19.18 124.46 90 top
R497  10K  [0402]  11.3 127.76 0 top
R498  10K  [0402]  7.24 127.76 180 top
R499  4.7K  [0402]  98.17 142.75 270 bottom
R500  4.7K  [0402]  99.44 142.75 270 bottom
R501  4.7K  [0402]  100.71 142.75 270 bottom
R502  10K  [0402]  101.98 137.79 270 bottom
R503  1K  [0402]  101.98 142.75 270 bottom
R504  10K  [0402]  103.25 137.79 270 bottom
R505  1K  [0402]  103.25 142.75 270 bottom
R506  10K  [0402]  104.52 137.79 270 bottom
R507  1K  [0402]  104.52 142.75 270 bottom
R508  10K  [0402]  105.79 137.79 270 bottom
R509  1K  [0402]  105.79 142.75 270 bottom
R511  33  [0402]  89.79 99.95 0 top
R513  1K  [0402]  89.79 100.97 0 top
R516  1K  [0402]  80.39 103.63 270 top
R517  33  [0402]  89.79 108.2 0 top
R518  1K  [0402]  89.79 109.22 0 top
R519  49.9  [0402]  243.33 135.89 0 top
R520  0  [0402]  241.3 135.89 0 top
R521  0  [0402]  241.3 137.16 0 top
R523  49.9  [0402]  243.33 137.16 0 top
R524  49.9  [0402]  238.38 143.64 270 top
R525  0  [0402]  238.38 141.6 90 top
R526  0  [0402]  237.11 141.6 90 top
R527  49.9  [0402]  235.97 143.64 90 top
R528  49.9  [0402]  237.11 143.64 270 top
R530  0  [0402]  235.97 141.6 90 top
R532  0  [0402]  234.7 141.6 90 top
R533  1K  [0402]  239.52 141.6 270 top
R534  49.9  [0402]  234.7 143.64 90 top
R535  49.9  [0402]  229.87 138.81 0 top
R536  0  [0402]  231.9 138.81 180 top
R537  0  [0402]  231.9 137.54 180 top
R538  49.9  [0402]  229.87 137.54 0 top
R540  1K  [0402]  226.44 68.45 90 top
R541  150  [0402]  157.61 68.33 180 top
R542  150  [0402]  157.61 69.98 180 top
R543  150  [0402]  153.67 73.03 180 top
R544  150  [0402]  153.67 74.55 180 top
R545  150  [0402]  236.6 73.79 180 top
R546  150  [0402]  236.6 75.06 180 top
R547  150  [0402]  225.93 73.03 0 top
R548  150  [0402]  225.93 74.35 0 top
R549  10  [0402]  146.94 62.99 0 top
R550  10  [0402]  225.42 68.45 90 top
R551  100  [0402]  113.54 81.28 180 top
R552  0  [0402]  111.51 79.12 0 bottom
R553  10  [0402]  113.54 81.28 180 bottom
R554  0  [0402]  111.51 78.11 0 bottom
R555  10  [0402]  113.54 80.26 180 bottom
R556  100  [0402]  113.54 80.26 180 top
R557  13K  [0402]  94.23 80.65 270 bottom
R558  10K  [0402]  104.9 93.73 90 bottom
R559  0  [0402]  103.12 89.03 90 bottom
R560  1K  [0402]  95.25 80.65 90 bottom
R561  0  [0402]  103 94.36 270 top
R562  3.57K  [0402]  117.35 93.09 270 bottom
R563  4.7K  [0402]  97.28 78.61 90 bottom
R564  10K  [0402]  95.76 83.19 0 bottom
R565  301  [0402]  108.08 84.96 0 bottom
R566  301  [0402]  108.08 83.95 0 bottom
R567  1  [1206]  115.44 88.65 180 top
R568  1K  [0402]  96.27 78.61 90 bottom
R569  4.7K  [0402]  95.76 85.6 0 bottom
R570  4.7K  [0402]  95.76 86.61 0 bottom
R573  4.7K  [0402]  95.76 84.58 0 bottom
R574  4.7K  [0402]  95.76 82.17 0 bottom
R575  1.78K  [0402]  93.73 83.19 0 bottom
R576  2.87K  [0402]  108.08 82.55 180 bottom
R577  10K  [0603]  118.11 99.31 180 top
R578  3.4K  [0402]  109.6 82.04 90 bottom
R579  0  [0402]  103 104.52 270 top
R580  2.87K  [0402]  108.08 81.53 180 bottom
R581  301  [0402]  104.39 88.01 90 bottom
R582  301  [0402]  105.41 88.01 90 bottom
R586  3.57K  [0402]  117.35 103.12 270 bottom
R588  0  [0402]  100.08 89.03 90 bottom
R589  0  [0402]  99.06 89.03 90 bottom
R590  301  [0402]  108.08 87 0 bottom
R591  301  [0402]  108.08 85.98 0 bottom
R592  1  [1206]  115.44 109.98 180 top
R593  10K  [0402]  100.84 78.61 90 bottom
R594  7.5K  [0402]  101.85 78.61 90 bottom
R595  75  [0402]  98.3 78.61 270 bottom
R596  20.0K  [0402]  87.25 84.84 0 top
R597  49.9K  [0402]  88.77 84.33 90 top
R598  46.4K  [0402]  89.79 78.74 180 top
R599  10K  [0402]  91.82 78.74 180 top
R654  1K  [0402]  131.57 114.43 90 top
R656  1K  [0402]  42.29 100.84 180 top
R657  0  [0402]  131.57 111.89 90 top
R659  0  [0402]  40.77 101.35 90 top
R660  10K  [0402]  127.76 114.94 0 top
R662  10K  [0402]  42.8 102.36 270 top
R663  10K  [0402]  19.05 73.91 270 top
R665  1K  [0402]  125.48 112.4 90 top
R666  1K  [0402]  41.78 104.65 90 top
R667  10K  [0402]  126.49 112.4 90 top
R669  10K  [0402]  40.77 104.65 90 top
R670  1K  [0402]  15.62 70.23 270 top
R671  10K  [0402]  16.64 70.23 270 top
R672  1K  [0402]  79.76 79.88 180 top
R673  1K  [0402]  44.45 91.57 270 top
R675  0  [0402]  78.23 80.39 90 top
R676  0  [0402]  43.43 91.57 90 top
R678  10K  [0402]  80.26 81.41 270 top
R679  10K  [0402]  42.8 93.98 270 top
R681  1K  [0402]  79.25 83.69 90 top
R682  1K  [0402]  42.29 95.5 180 top
R684  10K  [0402]  78.23 83.69 90 top
R685  10K  [0402]  40.77 95 90 top
R687  1K  [0402]  47.88 122.43 90 top
R688  0  [0402]  46.35 121.92 180 top
R689  0  [0402]  49.66 121.92 180 top
R690  10K  [0402]  43.81 121.41 90 top
R691  10K  [0402]  52.2 121.41 270 top
R692  1K  [0402]  46.48 115.7 180 top
R693  10K  [0402]  46.48 116.71 180 top
R694  10  [0402]  224.03 149.61 180 top
R695  1K  [0402]  229.62 149.61 180 top
R696  1K  [0402]  231.14 148.08 90 top
R697  100K  [0402]  228.35 143.64 0 top
R699  510  [0402]  24.26 10.03 0 top
R700  0  [1206]  34.67 241.05 0 top
R701  0  [1206]  64.26 137.79 0 top
R702  510  [0402]  29.59 10.03 180 top
R703  10K  [0402]  52.32 129.03 90 top
R704  10K  [0402]  52.32 131.06 270 top
R705  4.7K  [0402]  18.67 62.74 0 top
R706  4.7K  [0402]  11.3 70.23 270 top
R707  100  [0402]  18.67 60.71 180 top
R708  4.7K  [0402]  19.05 68.07 180 top
R709  3.74K  [0402]  12.32 70.23 90 top
R710  4.7K  [0402]  7.11 68.07 270 top
R711  100  [0402]  15.75 60.71 180 top
R712  4.7K  [0402]  13.34 70.23 270 top
R713  1K  [0402]  7.62 64.9 180 top
R714  100K  [0402]  15.75 61.72 180 top
R715  100K  [0402]  8.13 63.37 90 top
R716  200K  [1206]  95.76 35.94 270 bottom
R717  200K  [1206]  91.31 35.94 270 bottom
R718  200K  [1206]  86.87 35.94 270 bottom
R719  200K  [1206]  82.42 35.94 270 bottom
R720  200K  [1206]  113.54 35.94 270 bottom
R721  200K  [1206]  109.09 35.94 270 bottom
R722  200K  [1206]  104.65 35.94 270 bottom
R723  200K  [1206]  100.2 35.94 270 bottom
R724  619  [0402]  208.53 73.53 180 top
R725  619  [0402]  242.82 73.53 180 top
R726  10K  [0402]  102.62 87.5 180 bottom
R727  0  [0402]  87.76 78.74 0 top
R728  169K  [0402]  219.46 132.97 90 top
R729  10K  [0402]  201.8 78.36 0 top
R730  124K  [0402]  199.14 75.82 90 top
R731  10K  [0402]  222.12 135.51 0 top
R732  10K  [0402]  200.15 75.82 90 top
R733  1.65K  [0402]  203.83 78.87 90 top
R734  10K  [0402]  220.47 132.97 90 top
R735  2.05K  [0402]  224.16 136.02 90 top
R736  10K  [0402]  222.12 138.56 0 top
R737  10K  [0402]  201.8 79.38 180 top
R738  10K  [0402]  201.8 81.41 0 top
R739  10K  [0402]  222.12 136.52 180 top
R740  10K  [0402]  201.8 77.34 180 top
R741  10K  [0402]  222.12 134.49 180 top
R742  0  [0402]  199.9 78.23 0 bottom
R743  0  [0402]  220.22 135.38 0 bottom
R744  10K  [0402]  199.9 79.25 0 bottom
R745  5.9K  [0402]  220.22 136.4 0 bottom
R746  187K  [0402]  21.97 116.08 270 top
R747  226K  [0402]  21.97 105.28 270 top
R748  10K  [0402]  19.3 113.54 180 top
R749  10K  [0402]  19.3 102.74 180 top
R750  10K  [0402]  20.95 116.08 270 top
R751  2.21K  [0402]  17.27 113.03 270 top
R752  10K  [0402]  19.3 112.52 0 top
R753  10K  [0402]  19.3 110.49 180 top
R754  10K  [0402]  20.95 105.28 270 top
R755  2.43K  [0402]  17.27 102.23 270 top
R756  10K  [0402]  19.3 101.73 0 top
R757  10K  [0402]  19.3 99.7 180 top
R758  10K  [0402]  19.3 114.55 0 top
R759  10K  [0402]  19.3 103.76 0 top
R760  0  [0402]  21.21 113.67 180 bottom
R761  0  [0402]  21.21 102.87 180 bottom
R762  4.99K  [0402]  21.21 112.65 180 bottom
R763  3.83K  [0402]  21.21 101.85 180 bottom
R764  309K  [0402]  59.44 84.33 270 top
R765  412K  [0402]  21.97 94.49 270 top
R766  10K  [0402]  56.77 81.79 180 top
R767  10K  [0402]  19.3 91.95 180 top
R768  10K  [0402]  58.42 84.33 270 top
R769  2.55K  [0402]  54.74 81.28 270 top
R770  10K  [0402]  20.95 94.49 270 top
R771  10K  [0402]  18.8 89.41 90 bottom
R772  10K  [0402]  19.3 88.9 180 top
R773  10K  [0402]  56.77 80.77 0 top
R774  10K  [0402]  56.77 78.74 180 top
R775  2.32K  [0402]  17.27 91.44 270 top
R776  10K  [0402]  56.77 82.8 0 top
R777  10K  [0402]  19.3 92.96 0 top
R778  0  [0402]  58.67 81.92 180 bottom
R779  0  [0402]  21.21 92.08 180 bottom
R780  2.49K  [0402]  58.67 80.9 180 bottom
R781  1.78K  [0402]  21.21 91.06 180 bottom
R782  1K  [0402]  200.66 133.98 90 top
R783  0  [0402]  202.44 132.72 0 top
R784  10K  [0402]  200.91 131.19 90 top
R785  1K  [0402]  203.45 128.52 180 top
R786  10K  [0402]  201.93 129.03 270 top
R787  32.4K  [0402]  222.12 139.57 180 top
R797  20K  [0402]  90.55 137.79 270 bottom
R798  20K  [0402]  91.82 137.79 270 bottom
R799  20K  [0402]  88.01 137.79 270 bottom
R800  20K  [0402]  89.28 137.79 270 bottom
R801  20K  [0402]  94.36 137.79 90 bottom
R802  20K  [0402]  100.71 137.79 90 bottom
R803  20K  [0402]  99.44 137.79 90 bottom
R804  20K  [0402]  98.17 137.79 90 bottom
R806  4.32K  [0402]  203.45 126.49 180 top
R807  10K  [0402]  203.45 127.51 0 top
R808  4.7K  [0402]  77.72 129.16 0 bottom
R809  4.7K  [0402]  115.95 133.22 0 bottom
R810  4.7K  [0402]  115.95 132.21 0 bottom
R811  4.7K  [0402]  155.7 115.44 90 bottom
R812  4.7K  [0402]  89.41 129.16 0 bottom
R813  4.7K  [0402]  70.32 105.43 180 bottom
R814  49.9  [0402]  153.8 100.84 270 bottom
R815  1K  [0402]  50.93 141.35 180 top
R816  0  [0402]  45.34 134.37 270 top
R817  0  [0402]  48.89 133.86 0 top
R818  10K  [0402]  45.85 131.83 180 top
R819  10K  [0402]  47.88 131.83 180 top
R820  1K  [0402]  43.81 131.83 180 top
R821  10K  [0402]  43.81 132.84 180 top
R822  0  [0402]  153.92 52.58 270 top
R823  4.7K  [0402]  159 56.13 90 top
R824  0  [0402]  154.43 52.7 270 bottom
R825  0  [0402]  131.7 53.21 270 top
R826  0  [0402]  132.21 53.34 270 bottom
R827  0  [0402]  181.86 65.91 0 top
R828  0  [0402]  186.56 68.45 270 bottom
R829  1K  [0402]  231.9 132.97 0 top
R830  1K  [0402]  149.86 127.51 0 bottom
R831  10K  [0402]  150.37 129.03 270 bottom
R834  1K  [0402]  238.25 132.08 90 top
R835  49.9  [0402]  229.87 136.4 180 top
R836  0  [0402]  231.9 136.4 180 top
R837  0  [0402]  231.9 135.13 180 top
R838  49.9  [0402]  229.87 135.13 180 top
R839  10  [0402]  235.46 130.94 0 bottom
R841  10  [0402]  238.12 139.45 180 bottom
R842  1K  [0402]  231.9 131.95 0 top
R843  1K  [0402]  241.3 134.75 180 top
R844  1K  [0402]  231.9 133.98 0 top
R845  4.7K  [0402]  179.07 38.61 270 bottom
R846  4.7K  [0402]  179.07 35.56 270 bottom
R847  4.7K  [0402]  181.1 38.61 270 bottom
R848  4.7K  [0402]  180.59 35.56 270 bottom
R849  4.7K  [0402]  265.18 149.61 0 top
R850  4.7K  [0402]  265.18 148.59 0 top
R851  4.7K  [0402]  265.18 147.57 0 top
R852  4.7K  [0402]  265.18 146.56 0 top
R853  4.7K  [0402]  144.53 122.94 0 bottom
R854  4.7K  [0402]  181.86 67.18 0 top
R855  4.7K  [0402]  222.38 70.99 0 top
R856  4.7K  [0402]  256.67 70.99 0 top
R857  4.7K  [0402]  108.33 69.72 90 top
R858  4.7K  [0402]  109.35 69.72 90 top
R859  4.7K  [0402]  275.21 138.3 180 top
R860  1K  [0402]  272.42 138.3 180 top
R861  0  [1206]  174.37 241.05 0 top
R862  0  [1206]  104.52 241.05 0 top
R863  0  [1206]  244.22 241.05 0 top
R864  20K  [0402]  113.41 126.37 0 bottom
R865  51  [0402]  269.49 140.59 90 top
R866  51  [0402]  269.49 138.05 90 top
R867  51  [0402]  270.51 140.59 270 top
R868  33  [0402]  277.11 140.59 270 top
R869  51  [0402]  271.53 138.81 270 bottom
R870  4.7K  [0402]  24 71.88 0 top
SW1  SWITCH_DIP_8  [CON_SWITCH_X8]  77.22 141.35 90 top
SW2  SWITCH_DIP_8  [CON_SWITCH_X8]  89.92 141.35 90 top
SW3  SWITCH_DIP_8  [CON_SWITCH_X8]  102.62 141.35 90 top
SW4  SWITCH  [CON_SW_60X60_2P2_34]  16.52 2.52 0 top
SW5  SWITCH  [CON_SW_60X60_2P2_34]  7.02 2.52 0 top
T1  GST5009LF  [MAG_GST5009]  160.02 34.54 180 top
T2  GST5009LF  [MAG_GST5009]  144.14 34.54 180 top
T3  GST5009LF  [MAG_GST5009]  194.69 21.97 180 top
T4  GST5009LF  [MAG_GST5009]  244.22 34.04 180 top
T5  GST5009LF  [MAG_GST5009]  209.93 34.04 180 top
T6  GST5009LF  [MAG_GST5009]  235.33 48.64 180 top
T7  GST5009LF  [MAG_GST5009]  201.04 48.64 180 top
T8  GST5009LF  [MAG_GST5009]  261.37 34.04 180 top
T9  GST5009LF  [MAG_GST5009]  227.08 34.04 180 top
T10  GST5009LF  [MAG_GST5009]  252.48 48.64 180 top
T11  GST5009LF  [MAG_GST5009]  218.19 48.64 180 top
T12  C8140  [XFMR_C8140]  63.25 54.36 180 top
TP1  -  [TP]  158.11 106.84 180 bottom
TP2  -  [TP]  137.92 128.02 180 bottom
TP3  -  [TP]  174.12 107.64 180 bottom
TP4  -  [TP]  175.72 106.04 180 bottom
TP5  -  [TP]  171.82 107.24 180 bottom
TP6  -  [TP]  185.93 106.43 180 bottom
TP7  -  [TP]  185.93 105.41 180 bottom
TP8  -  [TP]  174.92 106.84 180 bottom
TP9  -  [TP]  185.93 104.39 180 bottom
TP10  -  [TP]  172.52 108.44 180 bottom
TP11  -  [TP]  170.92 114.85 180 bottom
TP12  -  [TP]  172.52 114.85 180 bottom
TP13  -  [TP]  170.92 118.05 180 bottom
TP14  -  [TP]  172.52 118.05 180 bottom
U1  T1040  [BGA_P080_780]  166.12 114.05 90 top
U2  74LVC16373  [TSSOP_48W]  129.29 126.75 0 bottom
U4  JS28F00AM29EWHA  [TSOP1_56]  112.14 128.65 180 top
U6  MT29F8G08ABABAWP-ITX:B  [TSOP1_48]  87.38 127.64 180 top
U7  TXBN0304RSV  [QFN_P040_D040_B260X180_16]  92.46 126.11 0 bottom
U8  74LVC1G86  [SC70_5]  110.49 119.89 90 top
U9  74LVC1G86  [SC70_5]  103.38 119.89 90 top
U10  74LVC1G86  [SC70_5]  106.93 119.89 90 top
U11  TXBN0304RSV  [QFN_P040_D040_B260X180_16]  92.46 131.95 0 bottom
U12  TXBN0304RSV  [QFN_P040_D040_B260X180_16]  161.04 89.92 270 top
U13  N25Q512A13GSF40F  [SO_16L]  262.64 136.91 0 top
U15  N25Q512A13GF840F  [WSON_8]  262.64 136.91 90 top
U18  TXBN0304RSV  [QFN_P040_D040_B260X180_16]  156.46 89.92 270 top
U19  PCA9546APW  [TSSOP_16]  256.29 149.61 270 top
U20  TXBN0304RSV  [QFN_P040_D040_B260X180_16]  68.58 143.13 0 top
U21  FXLP34P5X  [SC70_5]  76.71 99.57 180 bottom
U22  FXLP34P5X  [SC70_5]  68.58 139.45 90 top
U23  74LVC1G66  [SC70_5]  148.72 58.67 270 top
U24  74LVC1G66  [SC70_5]  148.72 55.88 270 top
U25  PI3PCIE3212  [QFN_P050_D040_B450X250_20_E3X1]  209.3 82.3 270 bottom
